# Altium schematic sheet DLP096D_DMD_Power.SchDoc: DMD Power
size 431 x 279 mm; Date: Not shown in title block; ApprovedBy: Not shown in title block; CheckedBy: Not shown in title block; Author: Not shown in title block; CompanyName: Not shown in title block; Engineer: Not shown in title block; Organization: Not shown in title block; Address1: Not shown in title block; Address2: Not shown in title block; Address3: Not shown in title block; Address4: Not shown in title block; DocumentNumber: 5; Revision: Use project parameter SCH_Rev; SheetNumber: 5; SheetTotal: 10; PageSetup: Record=PageOptions¦CenterHorizontal=True¦CenterVertical=True¦PrintScale=1.00¦XCorrection=1.00¦YCorrection=1.00¦PrintKind=0¦BorderSize=5000000¦LeftOffset=0¦BottomOffset=0¦Orientation=2¦PaperLength=1000¦PaperWidth=1000¦Scale=100¦PaperSource=15¦PrintQuality=600¦MediaType=1¦DitherType=10¦PaperKind=Letter¦PrintScaleMode=1
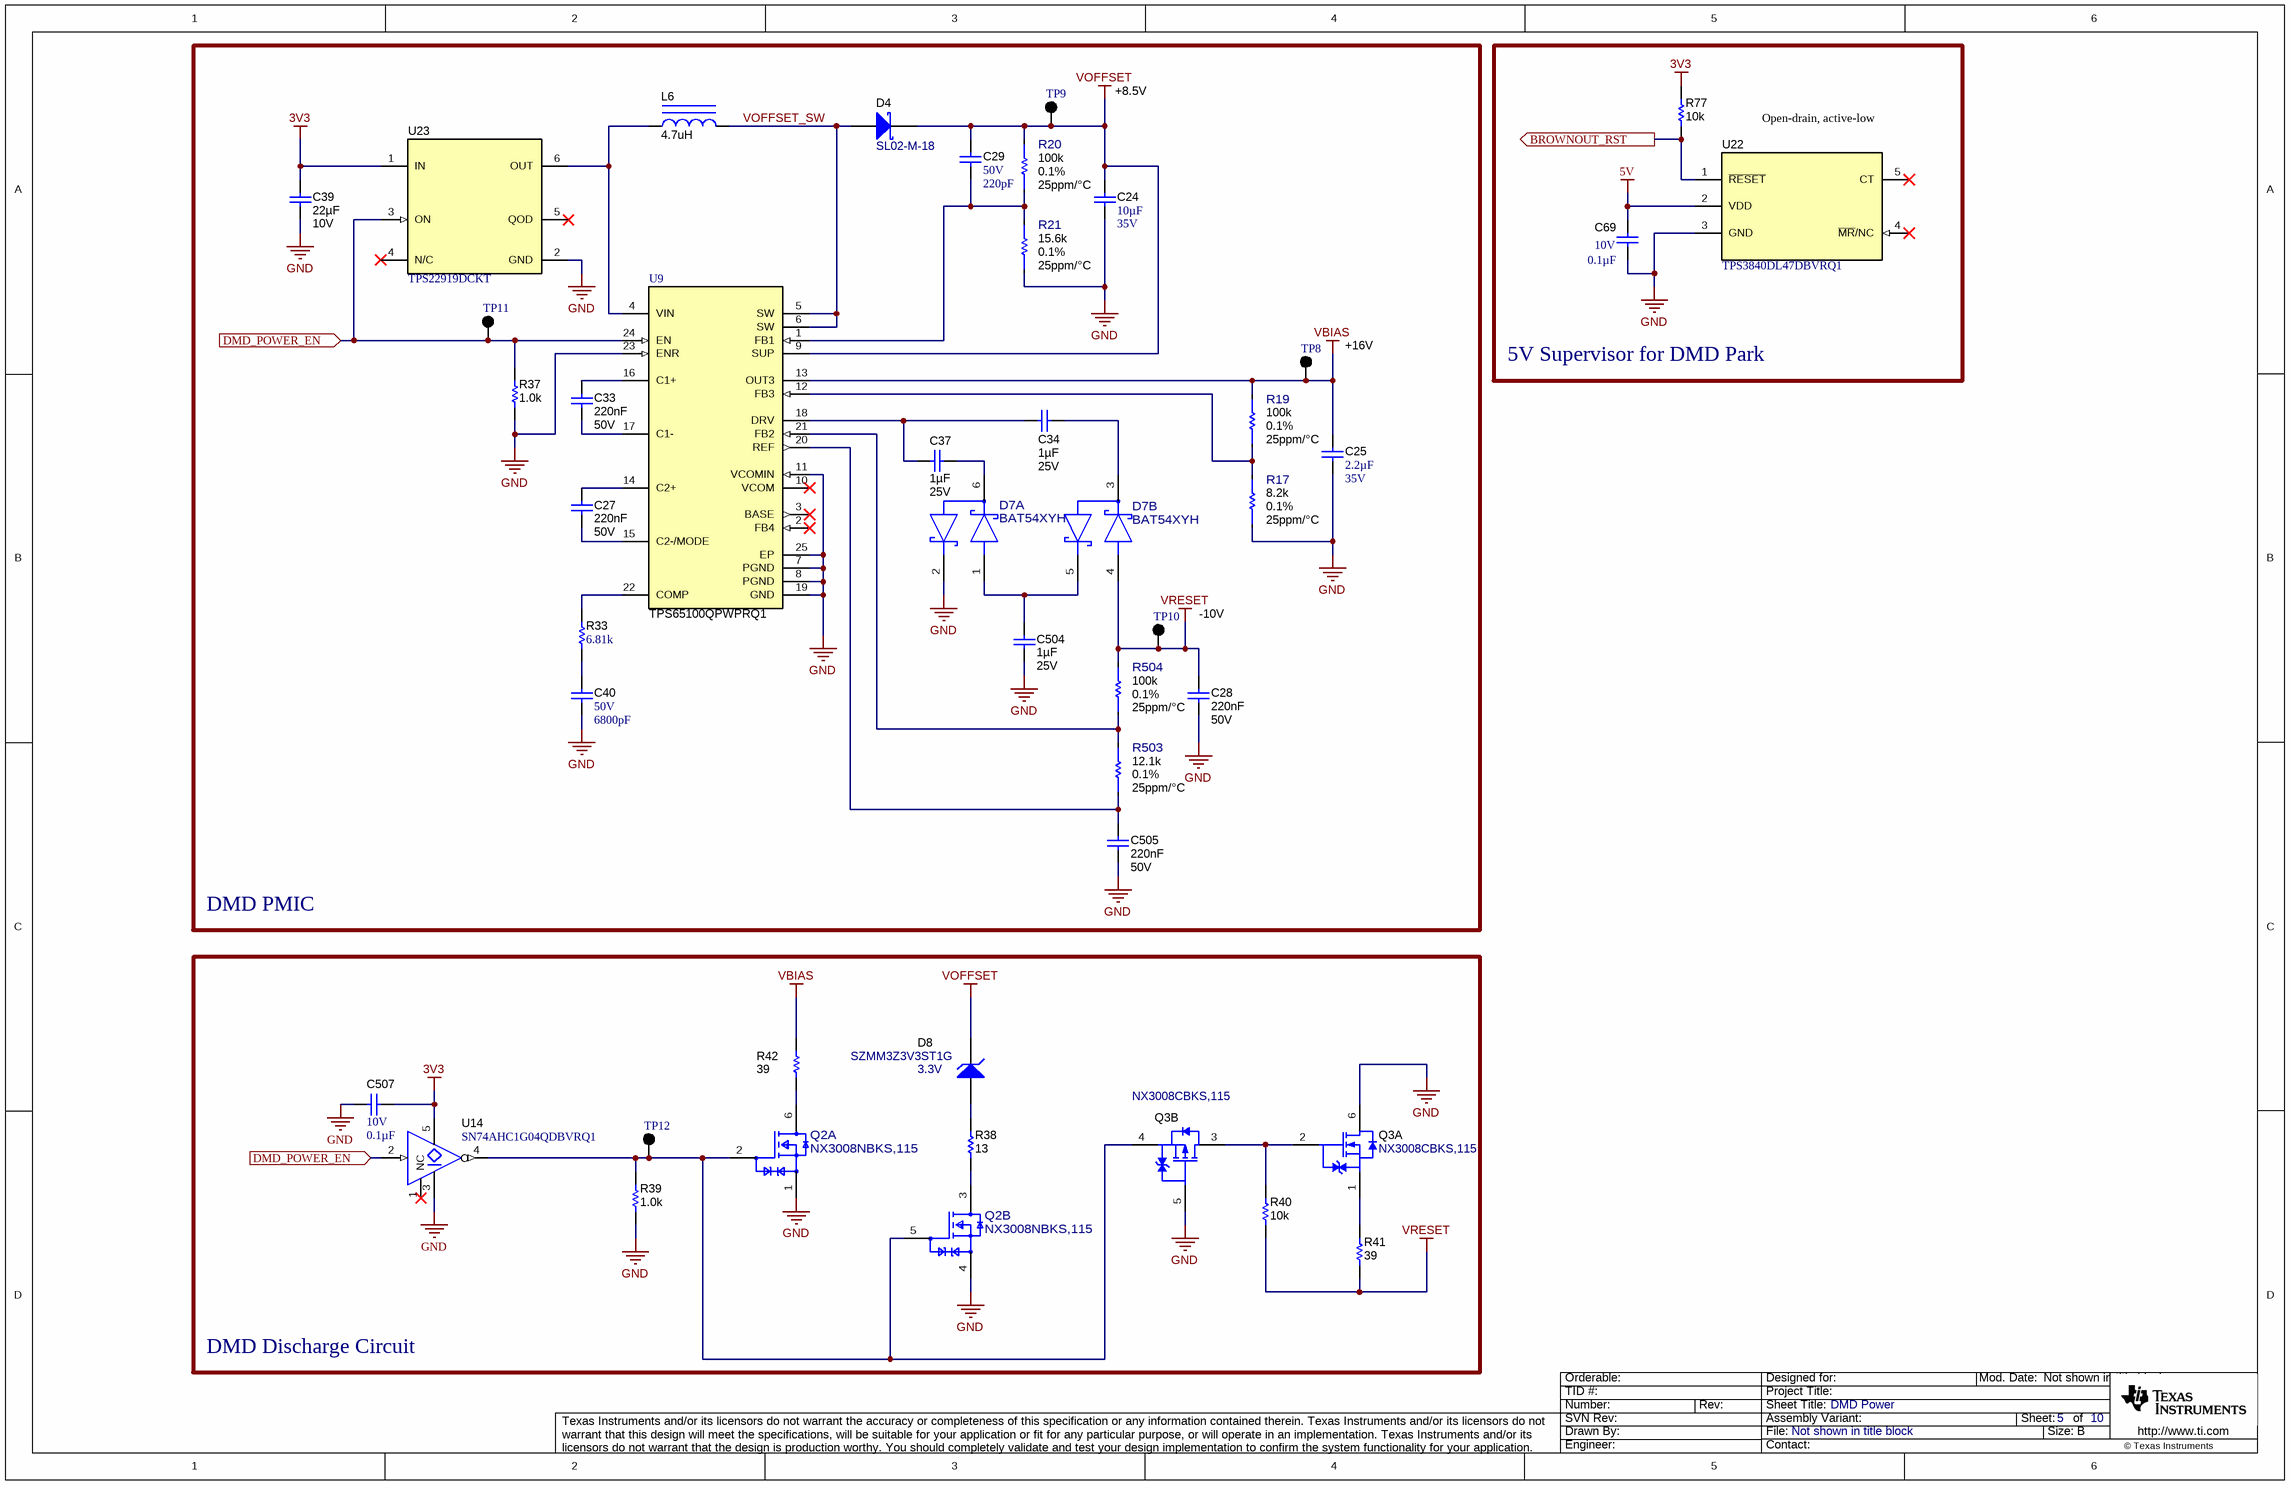
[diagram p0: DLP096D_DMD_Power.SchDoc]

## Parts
C24  Cap_F: 10µF  VDC_V: 35V  [0805_HV]  (hidden comment: C2012X5R1V106K085AC)
C25  Cap_F: 2.2µF  VDC_V: 35V  [0603]  (hidden comment: GRM188R6YA225KA12D)
C27  Cap_F: 220nF  VDC_V: 50V  [0603L]  (hidden comment: GCM188R71E104KA57D)
C28  Cap_F: 220nF  VDC_V: 50V  [0603L]  (hidden comment: GCM188R71E104KA57D)
C29  VDC_V: 50V  ValueDisplayed: 220pF  [0402]  (hidden comment: GRM155R71H221KA01D)
C33  Cap_F: 220nF  VDC_V: 50V  [0603L]  (hidden comment: GCM188R71E104KA57D)
C34  Cap_F: 1µF  VDC_V: 25V  [0603L]  (hidden comment: GCM188R71E105KA64D)
C37  Cap_F: 1µF  VDC_V: 25V  [0603L]  (hidden comment: GCM188R71E105KA64D)
C39  ValueDisplayed: 22µF  VDC_V: 10V  [1206_190L]  (hidden comment: CGA5L1X7S1A226M160AC)
C40  VDC_V: 50V  ValueDisplayed: 6800pF  [0402]  (hidden comment: CGA2B2X7R1H682K050BA)
C69  VDC_V: 10V  ValueDisplayed: 0.1µF  [0402]  (hidden comment: C0402C104K8RACTU)
C504  Cap_F: 1µF  VDC_V: 25V  [0603L]  (hidden comment: GCM188R71E105KA64D)
C505  Cap_F: 220nF  VDC_V: 50V  [0603L]  (hidden comment: CGA3E3X7R1H224K080AB)
C507  VDC_V: 10V  ValueDisplayed: 0.1µF  [0402]  (hidden comment: C0402C104K8RACTU)
D4  SL02-M-18  [DO-219AB]
D7  BAT54XYH  [FP-BAT54XYH_SOT363-IPC_C]  (parts A,B of 2)
D8  SZMM3Z3V3ST1G  value 3.3V  [SOD-323]
L6  ValueDisplayed: 4.7uH  [FDSD0420]  (hidden comment: FDSD0420D-4R7M)
Q2  NX3008NBKS,115  [FP-NX3008NBKS,115_TSSOP6-IPC_C]  (parts A,B of 2)
Q3  NX3008CBKS,115  [SOT-363]  (parts A,B of 2)
R17  Res_ohm: 8.2k  Tolerance_%: 0.1%  TempCo: 25ppm/°C  [FP-ERA-2AEB822X_0402-IPC_C]  (hidden comment: ERA-2AEB822X)
R19  TempCo: 25ppm/°C  Tolerance_%: 0.1%  Res_ohm: 100k  [FP-ERA-2AEB104X_0402-IPC_C]  (hidden comment: ERA-2AEB104X)
R20  TempCo: 25ppm/°C  Tolerance_%: 0.1%  Res_ohm: 100k  [FP-ERA-2AEB104X_0402-IPC_C]  (hidden comment: ERA-2AEB104X)
R21  Res_ohm: 15.6k  Tolerance_%: 0.1%  TempCo: 25ppm/°C  [FP-TNPW040215K6BEED_0402-IPC_C]  (hidden comment: TNPW040215K6BEED)
R33  ValueDisplayed: 6.81k  [0402]  (hidden comment: CRCW04026K81FKED)
R37  ValueDisplayed: 1.0k  [0402L]  (hidden comment: ERJ-2GEJ102X)
R38  ValueDisplayed: 13  [0402L]  (hidden comment: CRCW040213R0JNED)
R39  ValueDisplayed: 1.0k  [0402L]  (hidden comment: ERJ-2GEJ102X)
R40  ValueDisplayed: 10k  [0402L]  (hidden comment: ERJ-2GEJ103X)
R41  ValueDisplayed: 39  [0402L]  (hidden comment: CRCW040239R0JNED)
R42  ValueDisplayed: 39  [0402L]  (hidden comment: CRCW040239R0JNED)
R77  ValueDisplayed: 10k  [0402L]  (hidden comment: ERJ-2GEJ103X)
R503  TempCo: 25ppm/°C  Tolerance_%: 0.1%  Res_ohm: 12.1k  [FP-ERA-2AEB1212X_0402-MFG]  (hidden comment: ERA-2AEB1212X)
R504  TempCo: 25ppm/°C  Tolerance_%: 0.1%  Res_ohm: 100k  [FP-ERA-2AEB104X_0402-MFG]  (hidden comment: ERA-2AEB104X)
TP8  5001  [Keystone5001]  (value not drawn)
TP9  5001  [Keystone5001]  (value not drawn)
TP10  5001  [Keystone5001]  (value not drawn)
TP11  5001  [Keystone5001]  (value not drawn)
TP12  5001  [Keystone5001]  (value not drawn)
U9  TPS65100QPWPRQ1  [PWP0024B_NV_L]
U14  SN74AHC1G04QDBVRQ1  [DBV0005A_N]
U22  TPS3840DL47DBVRQ1  [DBV0005A_N]
U23  TPS22919DCKT  [DCK0006A_N]

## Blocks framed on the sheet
DMD PMIC: C24 C25 C27-C29 C33 C34 C37 C39 C40 C504 C505 D4 D7 L6 R17 R19-R21 R33 R37 R503 R504 TP8-TP11 U9 U23
5V Supervisor for DMD Park: C69 R77 U22
DMD Discharge Circuit: C507 D8 Q2 Q3 R38-R42 TP12 U14

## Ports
BROWNOUT_RST (out), DMD_POWER_EN (in)

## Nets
3V3: C39.2 C507.1 R77.2 U14.5(VCC) U23.1(IN)
5V: C69.1 U22.2(VDD)
GND: C24.2 C25.1 C28.2 C39.1 C40.1 C69.2 C504.2 C505.2 C507.2 D7.2(cathode_2) Q2.1(S1) Q2.4(S2) Q3.5(G) Q3.6(D) R17.1 R21.1 R37.1 R39.1 U9.7(PGND) U9.8(PGND) U9.11(VCOMIN) U9.19(GND) U9.23(ENR) U9.25(EP) U14.3(GND) U22.3(GND) U23.2(GND)
VBIAS: C25.2 R19.2 R42.2 TP8.1 U9.13(OUT3)
VOFFSET: C24.1 C29.1 D4.1(K) D8.1(K) R20.2 TP9.1 U9.9(SUP)
VRESET: C28.1 D7.4(anode4) R40.1 R41.1 R504.2 TP10.1
BROWNOUT_RST: R77.1 U22.1(~{RESET}) ; port BROWNOUT_RST
DMD_POWER_EN: R37.2 TP11.1 U9.24(EN) U14.2(A) U23.3(ON) ; port DMD_POWER_EN
VOFFSET_SW: D4.2(A) L6.2 U9.5(SW) U9.6(SW)
NetC27_1: C27.1 U9.14(C2+)
NetC27_2: C27.2 U9.15(C2-/MODE)
NetC29_2: C29.2 R20.1 R21.2 U9.1(FB1)
NetC33_1: C33.1 U9.16(C1+)
NetC33_2: C33.2 U9.17(C1-)
NetC34_1: C34.1 D7.3(anode3/cathode4)
NetC34_2: C34.2 C37.1 U9.18(DRV)
NetC37_2: C37.2 D7.6(cathode1/anode2)
NetC40_2: C40.2 R33.1
NetC504_1: C504.1 D7.1(anode_1) D7.5(cathode3)
NetC505_1: C505.1 R503.1 U9.20(REF)
NetD8_2: D8.2(A) R38.2
NetL6_1: L6.1 U9.4(VIN) U23.6(OUT)
NetQ2_2: Q2.2(G1) Q2.5(G2) Q3.4(S) R39.2 TP12.1 U14.4(Y)
NetQ2_3: Q2.3(D2) R38.1
NetQ2_6: Q2.6(D1) R42.1
NetQ3_1: Q3.1(S) R41.2
NetQ3_2: Q3.2(G) Q3.3(D) R40.2
NetR17_2: R17.2 R19.1 U9.12(FB3)
NetR33_2: R33.2 U9.22(COMP)
NetR503_2: R503.2 R504.1 U9.21(FB2)

Not connected (* = marked no-connect by the designer): U9 2(FB4)* 3(BASE)* 10(VCOM)*; U14 1(NC)*; U22 4(~{MR}/NC)* 5(CT)*; U23 4(N/C)* 5(QOD)*

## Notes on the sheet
- +8.5V
- Open-drain, active-low
- (near TP8) +16V
- -10V

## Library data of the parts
C24 = CMP-0007842-2: CAP, CERM, 10 uF, 35 V, +/- 10%, X5R, 0805; Manufacturer: TDK; SizeAreaWB_mm2: 6.75; SizeArea_mm2: 2.5; AEC Qualified: N; AEC Category: Q200; Value: 10uF; TaMax_C: 85°C; SizeZ_mm: 1.45; TaMin_C: -55°C; SizeY_mm: 1.25; U/M: EA; SizeX_mm: 2; Cap_Case: 0805; ESR_ohm: 2.818m; IRMS_A: 3.8868A; Value1: 0.002818 ohm
C25 = CMP-0007356-5: CAP, CERM, 2.2 uF, 35 V, +/- 10%, X5R, 0603; Manufacturer: MuRata; TaMin_C: -55°C; Polarized: N; SizeAreaWB_mm2: 4.68; Value1: Unknown; U/M: EA; Value: 2.2uF; TaMax_C: 85°C; SizeZ_mm: 1; SizeX_mm: 1.6; SizeY_mm: 0.8; SizeArea_mm2: 1.28; AEC Category: Q200
C27 C28 C33 = CMP-0007094-5: CAP, CERM, 0.22 uF, 50 V, +/- 10%, X7R, AEC-Q200 Grade 1, 0603; Manufacturer: TDK; PartNumber: CGA3E3X7R1H224K080AB; TaMin_C: -55°C; ESR_ohm: 0.021699; Polarized: N; SizeAreaWB_mm2: 4.68; Value1: 0.021699 ohm; U/M: EA; Value: 0.22uF; TaMax_C: 125°C; SizeZ_mm: 1; SizeX_mm: 1.6; SizeY_mm: 0.8; Cap_Case: 0603; SizeArea_mm2: 1.28; AEC Qualified: Y; IRMS_A: 1.12496A; AEC Category: Q200
C29 = CMP-0006682-2: CAP, CERM, 220 pF, 50 V, +/- 10%, X7R, 0402; Manufacturer: MuRata; SizeAreaWB_mm2: 3; SizeArea_mm2: 0.5; AEC Category: Q200; Value: 220pF; TaMax_C: 125°C; SizeZ_mm: 0.6; Polarized: N; TaMin_C: -55°C; U/M: EA; SizeX_mm: 1; Value1: Unknown
C34 C37 C504 = CMP-0007139-4: CAP, CERM, 1 uF, 25 V, +/- 10%, X7R, AEC-Q200 Grade 1, 0603; Manufacturer: MuRata; TaMin_C: -55°C; Polarized: N; SizeAreaWB_mm2: 4.68; Value1: Unknown; U/M: EA; Value: 1uF; TaMax_C: 125°C; SizeZ_mm: 1; SizeX_mm: 1.6; SizeY_mm: 0.8; Cap_Case: 0603; SizeArea_mm2: 1.28; AEC Qualified: Y; AEC Category: Q200
C39 = CMP-0088003-2: CAP CER 22UF 10V X7S 1206; Manufacturer: TDK; TempCo: 30ppm/°C; AEC Qualified: Yes; Tolerance_%: 20%; SizeZ_mm: 1.9mm; Value: 22µF
C40 = CMP-0006323-2: CAP, CERM, 6800 pF, 50 V, +/- 10%, X7R, AEC-Q200 Grade 1, 0402; Manufacturer: TDK; TaMin_C: -55°C; ESR_ohm: 0.3916; Polarized: N; SizeAreaWB_mm2: 3; Value1: 0.391597 ohm; U/M: EA; Value: 6800pF; TaMax_C: 125°C; SizeZ_mm: 0.6; SizeX_mm: 1; SizeY_mm: 0.5; AEC Qualified: Y; Cap_F: 6.8nF; IRMS_A: 315.526mA; AEC Category: Q200
C69 C507 = CMP-0078241-1: CAP, CERM, 0.1 µF, 10 V,+/- 10%, X7R, 0402; Manufacturer: Kemet; TaMin_C: -55°C; Polarized: N; SizeAreaWB_mm2: 3; U/M: EA; Value: 0.1uF; TaMax_C: 125°C; SizeZ_mm: 0.6; SizeX_mm: 1; SizeY_mm: 0.5; Cap_F: 100nF; AEC Category: Q200
C505 = CMP-0007094-5: CAP, CERM, 0.22 uF, 50 V, +/- 10%, X7R, AEC-Q200 Grade 1, 0603; Manufacturer: TDK; TaMin_C: -55°C; ESR_ohm: 0.021699; Polarized: N; SizeAreaWB_mm2: 4.68; Value1: 0.021699 ohm; U/M: EA; Value: 0.22uF; TaMax_C: 125°C; SizeZ_mm: 1; SizeX_mm: 1.6; SizeY_mm: 0.8; Cap_Case: 0603; SizeArea_mm2: 1.28; AEC Qualified: Y; IRMS_A: 1.12496A; AEC Category: Q200
D4 = CMP-0028814-3: Diode, Schottky, 20 V, 1.1 A, AEC-Q101, DO-219AB; Manufacturer: Vishay-Semiconductor; Io_A: 1.1A; Green_Lifecycle: Not Set; SizeAreaWB_mm2: 13.16; Vr_V: 20V; Green_REACh: Incomplete; TJmax_C: 125°C; Value: 20V; SizeZ_mm: 1.08; SizeX_mm: 3.7; SizeY_mm: 1.8; Vf_V: 420mV; Value2: 0.42V; SizeArea_mm2: 6.66; AEC Qualified: Y; AEC Category: Q101
D7 = CMP-0086617-1: Diode Array 2 Pair Series Connection Schottky 30V 200mA (DC) Surface Mount 6-TSSOP, SC-88, SOT-363; Manufacturer: Nexperia; SizeZ_mm: 1.1mm; TJmax_C: 125°C; AEC Qualified: Yes
D8 = CMP-0085730-1: Diode, Zener, 3.3 V, 300 mW, AEC-Q101, SOD-323; Manufacturer: ON Semiconductor; RJA_CperW: 416; AEC Qualified: Y; SizeArea_mm2: 3.645; SizeX_mm: 2.7; SizeY_mm: 1.35; SizeZ_mm: 1; AEC Category: Q101; SizeAreaWB_mm2: 8.695; Power_W: 300mW; Value1: 0.3W
L6 = CMP-0058987-1: Inductor, Shielded, 4.7 uH, 2.7 A, 0.083 ohm, AEC-Q200 Grade 1, SMD; Manufacturer: MuRata Toko; PartNumber: FDSD0420D-4R7M=P3; Isat: 2.7A @ 30% inductance drop; Irms: 3.6A @ 40C rise; SizeAreaWB_mm2: 27.04; DCR_ohm: 0.083; Value: 4.7uH; Imax_A: 2.7A; SizeZ_mm: 2; SizeX_mm: 4.2; SizeArea_mm2: 17.64; Ind_H: 4.7µH; AEC Qualified: Y; AEC Grade: 1; AEC Category: Q200
Q2 = CMP-0088579-4: MOSFET 2N-CH 30V 0.35A 6TSSOP; Manufacturer: Nexperia; AEC Qualified: Yes; ChMode: False; Rthja Max: 390K/W; Turn Off Delay Time: 69ns; Rdson45_ohm: 1; Number Of N Channels: 2; Vgs_V: 8V; Pulse Drain Current: 1.4A; TaMin_C: -55°C; TaMax_C: +150°C; Turn On Delay Time: 15ns; AEC Grade: Grade 0; Transconductance: 0.31S; Threshold Vgs Min: 0.6V; Threshold Vgs Max: 1.1V; Input Capacitace At Vds: 34pF @ 15V; SizeZ_mm: 1.1mm; IdsMax_A: 350mA; QgTyp_nC: 0.52nC @ 4.5V; Power_W: 445mW; Typ Forward Diode Voltage: 0.85V; VdsMax_V: 1.2V
Q3 = CMP-0082233-2: MOSFET, 2-CH, N/P-CH, -30 V, -0.2 A, AEC-Q101, SOT-363; Manufacturer: Nexperia; Alternate Manufacturer: None; SizeAreaWB_mm2: 10.24; Value2: 0.55 nC; Rdson45_ohm: 4.1; Value1: 4.1 ohm; SizeX_mm: 2.2; Value: -30V; ChMode: Enhancement; Vgs_V: -8V; SizeArea_mm2: 4.84; AEC Qualified: Y; AEC Category: Q101; ChType: P; QgTyp_nC: 0.55; IdsMax_A: -200mA; SizeZ_mm: 1.1
R17 = CMP-0088626-1: Res Thin Film 0402 8.2K Ohm 0.1% 0.063W(1/16W) ±25ppm/C Pad SMD Automotive T/R; Manufacturer: Panasonic Electronic Components; VDC_V: 50V; AEC Grade: Grade 0; SizeZ_mm: 0.4mm; AEC Qualified: Yes; Power_W: 63mW
R19 R20 R504 = CMP-0088648-1: Res Thin Film 0402 100K Ohm 0.1% 1/16W ±25ppm/°C Molded SMD SMD Punched Carrier T/R; Manufacturer: Panasonic; Category 7542B8484461Ae85: Passive Components; VDC_V: 50V; Category Cd01000Bfc2916C6: Single Components; Power_W: 63mW; Category 5A00970A6D5C81C7: Uncategorized; AEC Qualified: Yes; SizeZ_mm: 0.4mm; AEC Grade: Grade 0; Category 5C6A91606D4187Ad: Resistors
R21 = CMP-0088630-1: Res Thin Film 0402 15.6K Ohm 0.1% 1/10W ±25ppm/°C Molded SMD Paper T/R; Manufacturer: Vishay; Power_W: 100mW; SizeZ_mm: 0.4mm; AEC Qualified: Yes; AEC Grade: Grade 0; VDC_V: 50V
R33 = CMP-0026517-2: RES, 6.81 k, 1%, 0.063 W, AEC-Q200 Grade 0, 0402; Manufacturer: Vishay-Dale; Power_W: 63mW; TempCo: 100 ppm/C; Value_Code: 6k81; Value: 6.81k; EIA_Code: E96; SizeX_mm: 1; SizeY_mm: 0.5; SizeZ_mm: 0.6; Value2: 0.063W; AEC Qualified: Y; VDC_V: 50V; AEC Category: Q200; AEC Grade: 0
R37 R39 = CMP-0078193-1: RES, 1.0 k, 5%, 0.1 W, AEC-Q200 Grade 0, 0402; Manufacturer: Panasonic; Value_Code: 1k00; SizeArea_mm2: 0.5; AEC Qualified: Y; AEC Category: Q200; Res_ohm: 1k; Value: 1.0k; SizeZ_mm: 0.6; Green_REACh: Passed; EIA_Code: E24; TempCo: 200 ppm/C; AEC Grade: 0; Power_W: 100mW; VDC_V: 50V; Value2: 0.1W; Green_Lifecycle: Active; U/M: EA; SizeX_mm: 1
R38 = CMP-0026839-3: RES, 13, 5%, 0.063 W, AEC-Q200 Grade 0, 0402; Manufacturer: Vishay-Dale; Power_W: 63mW; TempCo: 200 ppm/C; Value_Code: 13R0; Value: 13; EIA_Code: E24; SizeX_mm: 1; SizeY_mm: 0.5; SizeZ_mm: 0.6; Value2: 0.063W; AEC Qualified: Y; VDC_V: 50V; AEC Category: Q200; AEC Grade: 0
R40 R77 = CMP-0026994-4: RES, 10 k, 5%, 0.1 W, AEC-Q200 Grade 0, 0402; Manufacturer: Panasonic; Power_W: 100mW; TempCo: 200 ppm/C; Value_Code: 10k0; U/M: EA; Value: 10k; EIA_Code: E24; SizeX_mm: 1; SizeY_mm: 0.5; SizeZ_mm: 0.6; Value2: 0.1W; AEC Qualified: Y; VDC_V: 50V; AEC Grade: 0; AEC Category: Q200
R41 R42 = CMP-0026916-3: RES, 39, 5%, 0.063 W, AEC-Q200 Grade 0, 0402; Manufacturer: Vishay-Dale; Power_W: 63mW; TempCo: 200 ppm/C; Value_Code: 39R0; Value: 39; EIA_Code: E24; SizeX_mm: 1; SizeY_mm: 0.5; SizeZ_mm: 0.6; Value2: 0.063W; AEC Qualified: Y; VDC_V: 50V; AEC Category: Q200; AEC Grade: 0
R503 = CMP-0088636-1: RES SMD 12.1KOHM 0.1% 1/16W 0402; Manufacturer: Panasonic Electronic Components; SizeZ_mm: 0.4mm; AEC Qualified: Yes; AEC Grade: Grade 0; Power_W: 63mW; VDC_V: 50V
TP8 TP10-TP12 = CMP-0055138-1: Test Point, Miniature, Black, TH; Manufacturer: Keystone; CNHeader: FALSE; Green_Lifecycle: Active; Green_REACh: Passed; ContactFinish: Silver; CT: TRUE
TP9 = CMP-0055138-2: Test Point, Miniature, Black, TH; Manufacturer: Keystone Electronics; CNHeader: FALSE; Green_Lifecycle: Active; Green_REACh: Passed; ContactFinish: Silver; CT: TRUE
U9 = CMP-0034937-2: Dimmable Quasi-Resonant LED Lighting Controller, 9 to 21.5 V, -40 to 140 degC, 16-pin SOP (PW16), Green (RoHS & no Sb/Br); Manufacturer: Texas Instruments; SubFamily: LCD/OLED Display Bias Solutions; Rating: Automotive; Topology: Boost, Inverting Buck/Boost; Vin(Max)(V): 5.8; Vin(Min)(V): 2.7; Iout(Max)(A): 0.35; Iq(Typ)(mA): 0.75; Synchronous Rectification: TRUE; Switching Frequency(Typ)(kHz): 1600
U14 = CMP-0051688-3: Automotive Catalog Single Inverter Gate, DBV0005A (SOT-23-5); Manufacturer: Texas Instruments; Generic Part Number: SN74AHC1G04-Q1; Output Type: CMOS; tpd @ Nom Voltage(Max)(ns): 10.6,7.5; Bits(#): 1; Schmitt Trigger: No; VCC(Max)(V): 5.5; CompType: IC; Voltage(Nom)(V): 3.3,5; SizeAreaWB_mm2: 14.82; SizeX_mm: 2.8; ICC @ Nom Voltage(Max)(mA): 0.01; F @ Nom Voltage(Max)(Mhz): 75; SizeY_mm: 2.9; Logic: Inverting; AEC Category: Q200; Output Drive (IOL/IOH)(Max)(mA): 50/-50; SizeArea_mm2: 8.12; AEC Qualified: Y; SizeZ_mm: 1.45; VCC(Min)(V): 2
U22 = CMP-0861099-1: Automotive high-input voltage supervisor with manual reset and programmable-reset time delay, DBV0005A (SOT-23-5); Manufacturer: Texas Instruments; SizeArea_mm2: 8.12; AEC Qualified: Y; AEC Category: Q200; SizeX_mm: 2.8; SizeY_mm: 2.9; CompType: IC; SizeAreaWB_mm2: 14.82; SizeZ_mm: 1.45
U23 = CMP-0081107-1: 5.5-V, 1.5-A, 100-mohm Load Switch with Output Discharge, DCK0006A (SOT-SC70-6); Alternate PartNumber: TPS22919DCKR; Alternate Manufacturer: Texas Instruments; SizeAreaWB_mm2: 9.3; SizeZ_mm: 1.1; SizeX_mm: 2.1; SizeY_mm: 2; SizeArea_mm2: 4.2; CompType: IC; AEC Qualified: N; AEC Category: Q200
